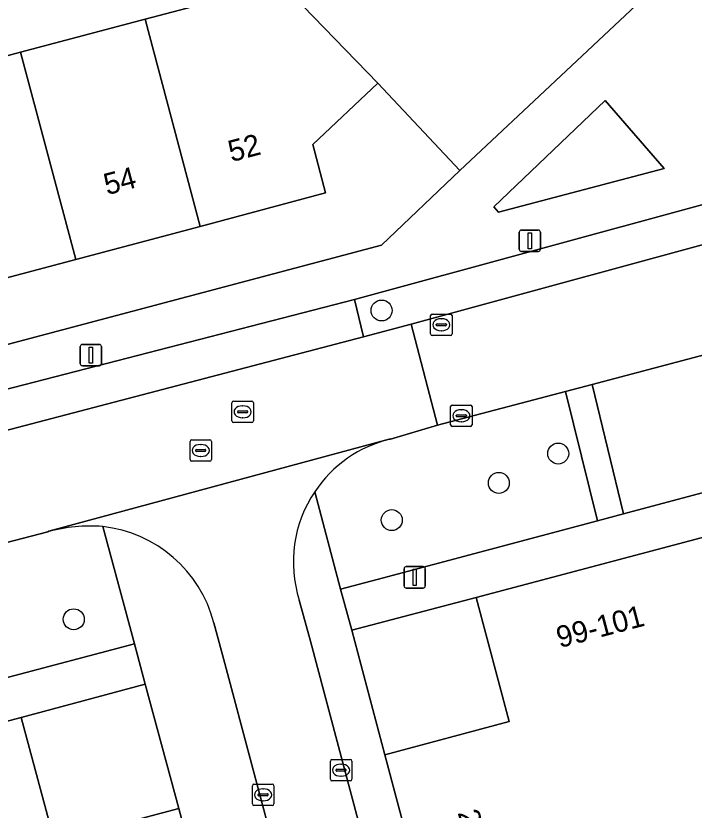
# Model space of a CAD drawing. Extents: x 162542 to 163147, y 380779 to 381521.
# Drawn here: x 162904.74 to 162936.38, y 381152.86 to 381189.91 of the extents above; entities that cross this region are included whole.
import ezdxf

# ---------------------------------------------------------------- set-up
doc = ezdxf.new("R2010")
doc.units = 0
for name, color, linetype in [('IMGEO_Boom', 7, 'Continuous'), ('IMGEO_Erf', 7, 'Continuous'), ('IMGEO_Groenvoorziening', 7, 'Continuous'), ('IMGEO_Kolk', 7, 'Continuous'), ('IMGEO_Lichtmast', 7, 'Continuous'), ('IMGEO_Muur', 7, 'Continuous'), ('IMGEO_Pand', 7, 'Continuous'), ('IMGEO_Pand_nummerreeks', 7, 'Continuous'), ('IMGEO_Parkeervlak_open', 7, 'Continuous'), ('IMGEO_Rijbaan_lokaal_open', 7, 'Continuous'), ('IMGEO_Rioolput', 7, 'Continuous'), ('IMGEO_Voetpad_open', 7, 'Continuous')]:
    doc.layers.add(name, color=color, linetype=linetype)

msp = doc.modelspace()

# ---------------------------------------------------------------- linework, layer by layer
at = {"layer": 'IMGEO_Boom'}
for centre in [(162921.8, 381176.17), (162930.038, 381169.497), (162927.268, 381168.127), (162922.276, 381166.393), (162907.441, 381161.767)]:
    msp.add_circle(centre, 0.489, dxfattribs=at)
at = {"layer": 'IMGEO_Erf'}
msp.add_lwpolyline([(162864.29, 381177.412), (162870.101, 381178.955), (162875.911, 381180.498), (162881.722, 381182.041), (162887.533, 381183.585), (162893.343, 381185.128), (162899.153, 381186.672), (162904.964, 381188.216), (162910.774, 381189.76), (162917.122, 381191.446)], dxfattribs=at)
for points in [[(162925.455, 381182.694), (162921.624, 381186.774), (162918.59, 381183.913), (162919.187, 381181.662), (162913.342, 381180.093), (162907.532, 381178.55), (162901.721, 381177.006), (162895.911, 381175.462), (162890.101, 381173.918), (162884.29, 381172.375), (162878.48, 381170.831), (162872.669, 381169.287), (162866.859, 381167.744), (162861.048, 381166.2), (162855.117, 381164.624), (162849.174, 381163.045), (162849.909, 381160.144), (162921.793, 381179.222)], [(162921.959, 381155.449), (162927.747, 381156.998), (162926.213, 381162.787), (162920.409, 381161.252)], [(162904.989, 381157.182), (162906.54, 381151.404), (162912.337, 381152.94), (162910.777, 381158.734)]]:
    msp.add_lwpolyline(points, close=True, dxfattribs=at)
at = {"layer": 'IMGEO_Groenvoorziening'}
for points in [[(162934.984, 381182.801), (162932.236, 381185.965), (162927.031, 381181), (162927.248, 381180.762)], [(162941.6, 381175.367), (162931.623, 381172.725), (162933.078, 381166.682), (162943.223, 381169.386)]]:
    msp.add_lwpolyline(points, close=True, dxfattribs=at)
for points in [[(162918.68, 381167.708), (162919.888, 381163.169), (162921.592, 381163.621), (162931.869, 381166.36), (162930.38, 381172.396)], [(162930.38, 381172.396), (162924.413, 381170.816), (162922.209, 381170.17)], [(162906.236, 381165.843), (162903.106, 381165.042), (162896.342, 381163.214), (162898.043, 381157.387), (162910.268, 381160.623), (162908.793, 381166.091)]]:
    msp.add_lwpolyline(points, dxfattribs=at)
for centre, radius, start, end in [((162923.519, 381164.532), 5.788, 103.0795, 146.7235), ((162908.186, 381159.041), 7.076, 85.0809, 105.9986)]:
    msp.add_arc(centre, radius, start, end, dxfattribs=at)
at = {"layer": 'IMGEO_Kolk'}
for p, q in [((162924.161, 381176.005), (162925.013, 381176.005)), ((162924.086, 381175.079), (162924.086, 381175.931)), ((162924.574, 381175.785), (162924.599, 381175.785)), ((162925.087, 381175.931), (162925.087, 381175.079)), ((162924.345, 381175.499), (162924.345, 381175.511)), ((162924.783, 381175.462), (162924.385, 381175.462)), ((162924.388, 381175.548), (162924.786, 381175.548)), ((162924.597, 381175.225), (162924.572, 381175.225)), ((162924.829, 381175.511), (162924.829, 381175.499)), ((162925.013, 381175.005), (162924.161, 381175.005)), ((162925.02, 381170.835), (162925.02, 381171.687)), ((162925.095, 381171.761), (162925.947, 381171.761)), ((162925.508, 381171.541), (162925.533, 381171.541)), ((162926.021, 381171.687), (162926.021, 381170.835)), ((162925.279, 381171.255), (162925.279, 381171.267)), ((162925.717, 381171.218), (162925.319, 381171.218)), ((162925.322, 381171.304), (162925.72, 381171.304)), ((162925.763, 381171.267), (162925.763, 381171.255)), ((162925.531, 381170.981), (162925.506, 381170.981)), ((162925.947, 381170.761), (162925.095, 381170.761)), ((162919.485, 381155.228), (162920.337, 381155.228)), ((162919.41, 381154.302), (162919.41, 381155.154)), ((162919.898, 381155.008), (162919.923, 381155.008)), ((162920.411, 381155.154), (162920.411, 381154.302)), ((162919.669, 381154.722), (162919.669, 381154.734)), ((162920.107, 381154.685), (162919.709, 381154.685)), ((162919.712, 381154.771), (162920.11, 381154.771)), ((162920.153, 381154.734), (162920.153, 381154.722)), ((162920.337, 381154.228), (162919.485, 381154.228)), ((162919.921, 381154.448), (162919.896, 381154.448)), ((162915.773, 381153.152), (162915.773, 381154.004)), ((162915.848, 381154.078), (162916.7, 381154.078)), ((162916.261, 381153.858), (162916.286, 381153.858)), ((162916.774, 381154.004), (162916.774, 381153.152)), ((162916.032, 381153.572), (162916.032, 381153.584)), ((162916.47, 381153.535), (162916.072, 381153.535)), ((162916.075, 381153.621), (162916.473, 381153.621)), ((162916.516, 381153.584), (162916.516, 381153.572)), ((162916.7, 381153.078), (162915.848, 381153.078)), ((162916.284, 381153.298), (162916.259, 381153.298))]:
    msp.add_line(p, q, dxfattribs=at)
for points in [[(162924.161, 381176.005), (162925.013, 381176.005)], [(162924.086, 381175.079), (162924.086, 381175.931)], [(162925.087, 381175.931), (162925.087, 381175.079)], [(162925.013, 381175.005), (162924.161, 381175.005)], [(162925.02, 381170.835), (162925.02, 381171.687)], [(162925.095, 381171.761), (162925.947, 381171.761)], [(162926.021, 381171.687), (162926.021, 381170.835)], [(162925.947, 381170.761), (162925.095, 381170.761)], [(162919.485, 381155.228), (162920.337, 381155.228)], [(162919.41, 381154.302), (162919.41, 381155.154)], [(162920.411, 381155.154), (162920.411, 381154.302)], [(162920.337, 381154.228), (162919.485, 381154.228)], [(162915.773, 381153.152), (162915.773, 381154.004)], [(162915.848, 381154.078), (162916.7, 381154.078)], [(162916.774, 381154.004), (162916.774, 381153.152)], [(162916.7, 381153.078), (162915.848, 381153.078)]]:
    msp.add_lwpolyline(points, dxfattribs=at)
for centre, radius, start, end in [((162924.163, 381175.929), 0.0765, 91.552, 178.448), ((162924.163, 381175.929), 0.0765, 91.552, 178.448), ((162925.011, 381175.929), 0.0765, 1.552, 88.448), ((162925.011, 381175.929), 0.0765, 1.552, 88.448), ((162924.385, 381175.508), 0.0403, 85.8775, 175.7526), ((162924.382, 381175.498), 0.0366, 178.938, 274.7102), ((162924.786, 381175.505), 0.043, 264.8664, 352.4533), ((162924.79, 381175.51), 0.0386, 1.7309, 96.639), ((162924.163, 381175.081), 0.0765, 181.552, 268.448), ((162924.163, 381175.081), 0.0765, 181.552, 268.448), ((162925.011, 381175.081), 0.0765, 271.552, 358.448), ((162925.011, 381175.081), 0.0765, 271.552, 358.448), ((162925.097, 381171.685), 0.0765, 91.552, 178.448), ((162925.097, 381171.685), 0.0765, 91.552, 178.448), ((162925.945, 381171.685), 0.0765, 1.552, 88.448), ((162925.945, 381171.685), 0.0765, 1.552, 88.448), ((162925.319, 381171.264), 0.0403, 85.8775, 175.7526), ((162925.316, 381171.254), 0.0366, 178.938, 274.7102), ((162925.72, 381171.261), 0.043, 264.8664, 352.4533), ((162925.724, 381171.266), 0.0386, 1.7309, 96.639), ((162925.097, 381170.837), 0.0765, 181.552, 268.448), ((162925.097, 381170.837), 0.0765, 181.552, 268.448), ((162925.945, 381170.837), 0.0765, 271.552, 358.448), ((162925.945, 381170.837), 0.0765, 271.552, 358.448), ((162919.487, 381155.152), 0.0765, 91.552, 178.448), ((162919.487, 381155.152), 0.0765, 91.552, 178.448), ((162920.335, 381155.152), 0.0765, 1.552, 88.448), ((162920.335, 381155.152), 0.0765, 1.552, 88.448), ((162919.709, 381154.731), 0.0403, 85.8775, 175.7526), ((162919.706, 381154.721), 0.0366, 178.938, 274.7102), ((162920.11, 381154.728), 0.043, 264.8664, 352.4533), ((162920.114, 381154.733), 0.0386, 1.7309, 96.639), ((162919.487, 381154.304), 0.0765, 181.552, 268.448), ((162919.487, 381154.304), 0.0765, 181.552, 268.448), ((162920.335, 381154.304), 0.0765, 271.552, 358.448), ((162920.335, 381154.304), 0.0765, 271.552, 358.448), ((162915.85, 381154.002), 0.0765, 91.552, 178.448), ((162915.85, 381154.002), 0.0765, 91.552, 178.448), ((162916.698, 381154.002), 0.0765, 1.552, 88.448), ((162916.698, 381154.002), 0.0765, 1.552, 88.448), ((162916.072, 381153.581), 0.0403, 85.8775, 175.7526), ((162916.069, 381153.571), 0.0366, 178.938, 274.7102), ((162916.473, 381153.578), 0.043, 264.8664, 352.4533), ((162916.477, 381153.583), 0.0386, 1.7309, 96.639), ((162915.85, 381153.154), 0.0765, 181.552, 268.448), ((162915.85, 381153.154), 0.0765, 181.552, 268.448), ((162916.698, 381153.154), 0.0765, 271.552, 358.448), ((162916.698, 381153.154), 0.0765, 271.552, 358.448)]:
    msp.add_arc(centre, radius, start, end, dxfattribs=at)
for centre, major_axis, ratio, start_param, end_param in [((162924.573, 381175.505), (-0.387, 0.002), 0.722429, 4.712389, 7.853982), ((162924.598, 381175.505), (-0.39, 0.002), 0.717154, 1.570796, 4.712389), ((162925.507, 381171.261), (-0.387, 0.002), 0.722429, 4.712389, 7.853982), ((162925.532, 381171.261), (-0.39, 0.002), 0.717154, 1.570796, 4.712389), ((162919.897, 381154.728), (-0.387, 0.002), 0.722429, 4.712389, 7.853982), ((162919.922, 381154.728), (-0.39, 0.002), 0.717154, 1.570796, 4.712389), ((162916.26, 381153.578), (-0.387, 0.002), 0.722429, 4.712389, 7.853982), ((162916.285, 381153.578), (-0.39, 0.002), 0.717154, 1.570796, 4.712389)]:
    msp.add_ellipse(centre, major_axis=major_axis, ratio=ratio, start_param=start_param, end_param=end_param, dxfattribs=at)
at = {"layer": 'IMGEO_Lichtmast'}
for p, q in [((162928.219, 381179.024), (162928.219, 381179.824)), ((162928.219, 381179.824), (162928.219, 381179.024)), ((162928.319, 381179.924), (162929.109, 381179.924)), ((162929.109, 381179.924), (162928.319, 381179.924)), ((162929.209, 381179.824), (162929.209, 381179.024)), ((162929.209, 381179.024), (162929.209, 381179.824)), ((162929.109, 381178.924), (162928.319, 381178.924)), ((162928.319, 381178.924), (162929.109, 381178.924)), ((162907.745, 381173.69), (162907.745, 381174.49)), ((162907.745, 381174.49), (162907.745, 381173.69)), ((162907.845, 381174.59), (162908.635, 381174.59)), ((162908.635, 381174.59), (162907.845, 381174.59)), ((162908.735, 381174.49), (162908.735, 381173.69)), ((162908.735, 381173.69), (162908.735, 381174.49)), ((162908.635, 381173.59), (162907.845, 381173.59)), ((162907.845, 381173.59), (162908.635, 381173.59)), ((162922.848, 381163.324), (162922.848, 381164.124)), ((162922.848, 381164.124), (162922.848, 381163.324)), ((162922.948, 381164.224), (162923.738, 381164.224)), ((162923.738, 381164.224), (162922.948, 381164.224)), ((162923.838, 381164.124), (162923.838, 381163.324)), ((162923.838, 381163.324), (162923.838, 381164.124)), ((162923.738, 381163.224), (162922.948, 381163.224)), ((162922.948, 381163.224), (162923.738, 381163.224))]:
    msp.add_line(p, q, dxfattribs=at)
for points in [[(162928.639, 381179.799), (162928.789, 381179.799), (162928.789, 381179.049), (162928.639, 381179.049), (162928.639, 381179.799)], [(162908.165, 381174.465), (162908.315, 381174.465), (162908.315, 381173.715), (162908.165, 381173.715), (162908.165, 381174.465)], [(162923.268, 381164.099), (162923.418, 381164.099), (162923.418, 381163.349), (162923.268, 381163.349), (162923.268, 381164.099)]]:
    msp.add_lwpolyline(points, dxfattribs=at)
for centre, start, end in [((162928.319, 381179.824), 90, 180), ((162928.319, 381179.824), 90, 180), ((162929.109, 381179.824), 0, 90), ((162929.109, 381179.824), 360, 90), ((162928.319, 381179.024), 180, 270), ((162928.319, 381179.024), 180, 270), ((162929.109, 381179.024), 270, 0), ((162929.109, 381179.024), 270, 0), ((162907.845, 381174.49), 90, 180), ((162907.845, 381174.49), 90, 180), ((162908.635, 381174.49), 0, 90), ((162908.635, 381174.49), 360, 90), ((162907.845, 381173.69), 180, 270), ((162907.845, 381173.69), 180, 270), ((162908.635, 381173.69), 270, 0), ((162908.635, 381173.69), 270, 0), ((162922.948, 381164.124), 90, 180), ((162922.948, 381164.124), 90, 180), ((162923.738, 381164.124), 0, 90), ((162923.738, 381164.124), 360, 90), ((162922.948, 381163.324), 180, 270), ((162922.948, 381163.324), 180, 270), ((162923.738, 381163.324), 270, 0), ((162923.738, 381163.324), 270, 0)]:
    msp.add_arc(centre, 0.1, start, end, dxfattribs=at)
at = {"layer": 'IMGEO_Muur'}
for points in [[(162926.213, 381162.787), (162920.409, 381161.252), (162921.959, 381155.449)], [(162910.777, 381158.734), (162904.989, 381157.182)], [(162912.337, 381152.94), (162910.777, 381158.734)]]:
    msp.add_lwpolyline(points, dxfattribs=at)
at = {"layer": 'IMGEO_Pand'}
for points in [[(162939.164, 381203.82), (162934.676, 381208.594), (162930.637, 381212.889), (162926.266, 381208.779), (162922.498, 381212.786), (162922.327, 381212.968), (162917.212, 381208.149), (162917.043, 381208.328), (162913.41, 381204.905), (162910.674, 381202.328), (162908.709, 381200.476), (162910.511, 381198.541), (162910.938, 381198.083), (162912.597, 381196.303), (162913.121, 381195.741), (162917.122, 381191.446), (162921.624, 381186.774), (162925.455, 381182.694), (162930.161, 381187.114), (162938.919, 381195.337), (162934.812, 381199.7)], [(162913.342, 381180.093), (162919.187, 381181.662), (162918.59, 381183.913), (162921.624, 381186.774), (162917.122, 381191.446), (162910.774, 381189.76)], [(162904.964, 381188.216), (162907.532, 381178.55), (162913.342, 381180.093), (162910.774, 381189.76)], [(162901.721, 381177.006), (162907.532, 381178.55), (162904.964, 381188.216), (162899.153, 381186.672)], [(162947.385, 381154.948), (162945.58, 381161.738), (162945.126, 381161.616), (162942.447, 381160.897), (162939.768, 381160.178), (162938.228, 381165.977), (162926.213, 381162.787), (162927.747, 381156.998), (162921.959, 381155.449), (162925.16, 381143.411), (162930.943, 381144.949), (162932.49, 381139.157), (162944.529, 381142.345), (162943.016, 381148.152), (162948.785, 381149.681), (162948.742, 381149.846)], [(162912.337, 381152.94), (162906.54, 381151.404), (162904.989, 381157.182), (162892.949, 381153.986), (162894.491, 381148.211), (162889.15, 381146.754), (162890.948, 381139.991), (162892.347, 381134.732), (162897.698, 381136.153), (162899.268, 381130.359), (162911.299, 381133.566), (162909.754, 381139.342), (162915.553, 381140.895)]]:
    msp.add_lwpolyline(points, close=True, dxfattribs=at)
at = {"layer": 'IMGEO_Parkeervlak_open'}
for points in [[(162945.307, 381183.409), (162944.204, 381183.118), (162943.854, 381183.025), (162937.074, 381181.191), (162920.542, 381176.676), (162920.963, 381174.947), (162923.178, 381175.528), (162939.834, 381180.075), (163029.671, 381203.749), (163029.17, 381205.595), (163009.881, 381200.547), (163008.469, 381200.178), (162968.263, 381189.504)], [(162920.963, 381174.947), (162920.542, 381176.676), (162903.648, 381172.331), (162904.167, 381170.544)]]:
    msp.add_lwpolyline(points, close=True, dxfattribs=at)
msp.add_lwpolyline([(162908.793, 381166.091), (162910.268, 381160.623), (162910.777, 381158.734), (162912.337, 381152.94), (162915.553, 381140.895), (162917.102, 381135.094), (162920.792, 381136.062), (162914.487, 381159.706), (162913.973, 381161.602)], dxfattribs=at)
msp.add_arc((162908.139, 381160.103), 6.023, 14.4079, 83.7675, dxfattribs=at)
at = {"layer": 'IMGEO_Rijbaan_lokaal_open'}
for points in [[(163029.671, 381203.749), (162939.834, 381180.075), (162923.178, 381175.528), (162924.413, 381170.816), (162930.38, 381172.396), (162931.623, 381172.725), (162941.6, 381175.367), (162946.927, 381176.777), (162948.093, 381177.085), (162958.186, 381179.749), (162960.101, 381180.253), (162970.109, 381182.891), (162971.268, 381183.196), (162981.715, 381185.95), (162982.865, 381186.253), (162993.306, 381189.004), (162994.468, 381189.311), (163004.787, 381192.03)], [(162922.209, 381170.17), (162922.157, 381170.174), (162906.287, 381165.874), (162906.236, 381165.843)], [(162918.477, 381160.741), (162917.962, 381162.664)], [(162913.973, 381161.602), (162914.487, 381159.706), (162920.792, 381136.062), (162924.771, 381137.113), (162918.477, 381160.741)]]:
    msp.add_lwpolyline(points, dxfattribs=at)
msp.add_lwpolyline([(162922.157, 381170.174), (162922.209, 381170.17), (162924.413, 381170.816), (162923.178, 381175.528), (162920.963, 381174.947), (162904.167, 381170.544), (162901.876, 381169.92), (162903.106, 381165.042), (162906.236, 381165.843), (162906.287, 381165.874)], close=True, dxfattribs=at)
for centre, radius, start, end in [((162923.519, 381164.532), 5.788, 103.0795, 146.7235), ((162923.504, 381164.448), 5.822, 145.9507, 197.8464), ((162908.186, 381159.041), 7.076, 85.0809, 105.9986), ((162908.139, 381160.103), 6.023, 14.4079, 83.7675)]:
    msp.add_arc(centre, radius, start, end, dxfattribs=at)
at = {"layer": 'IMGEO_Rioolput'}
for p, q in [((162914.892, 381171.944), (162915.744, 381171.944)), ((162914.817, 381171.018), (162914.817, 381171.87)), ((162915.305, 381171.724), (162915.33, 381171.724)), ((162915.818, 381171.87), (162915.818, 381171.018)), ((162915.076, 381171.438), (162915.076, 381171.45)), ((162915.514, 381171.401), (162915.116, 381171.401)), ((162915.119, 381171.487), (162915.517, 381171.487)), ((162915.328, 381171.164), (162915.303, 381171.164)), ((162915.56, 381171.45), (162915.56, 381171.438)), ((162915.744, 381170.944), (162914.892, 381170.944)), ((162912.864, 381169.214), (162912.864, 381170.066)), ((162912.939, 381170.14), (162913.791, 381170.14)), ((162913.865, 381170.066), (162913.865, 381169.214)), ((162913.166, 381169.683), (162913.564, 381169.683)), ((162913.352, 381169.92), (162913.377, 381169.92)), ((162913.123, 381169.634), (162913.123, 381169.646)), ((162913.561, 381169.597), (162913.163, 381169.597)), ((162913.375, 381169.36), (162913.35, 381169.36)), ((162913.607, 381169.646), (162913.607, 381169.634)), ((162913.791, 381169.14), (162912.939, 381169.14))]:
    msp.add_line(p, q, dxfattribs=at)
for points in [[(162914.892, 381171.944), (162915.744, 381171.944)], [(162914.817, 381171.018), (162914.817, 381171.87)], [(162915.818, 381171.87), (162915.818, 381171.018)], [(162915.744, 381170.944), (162914.892, 381170.944)], [(162912.864, 381169.214), (162912.864, 381170.066)], [(162912.939, 381170.14), (162913.791, 381170.14)], [(162913.865, 381170.066), (162913.865, 381169.214)], [(162913.791, 381169.14), (162912.939, 381169.14)]]:
    msp.add_lwpolyline(points, dxfattribs=at)
for centre, radius, start, end in [((162914.894, 381171.868), 0.0765, 91.552, 178.448), ((162914.894, 381171.868), 0.0765, 91.552, 178.448), ((162915.742, 381171.868), 0.0765, 1.552, 88.448), ((162915.742, 381171.868), 0.0765, 1.552, 88.448), ((162915.116, 381171.447), 0.0403, 85.8775, 175.7526), ((162915.113, 381171.437), 0.0366, 178.938, 274.7102), ((162915.517, 381171.444), 0.043, 264.8664, 352.4533), ((162915.521, 381171.449), 0.0386, 1.7309, 96.639), ((162914.894, 381171.02), 0.0765, 181.552, 268.448), ((162914.894, 381171.02), 0.0765, 181.552, 268.448), ((162915.742, 381171.02), 0.0765, 271.552, 358.448), ((162915.742, 381171.02), 0.0765, 271.552, 358.448), ((162912.941, 381170.064), 0.0765, 91.552, 178.448), ((162912.941, 381170.064), 0.0765, 91.552, 178.448), ((162913.789, 381170.064), 0.0765, 1.552, 88.448), ((162913.789, 381170.064), 0.0765, 1.552, 88.448), ((162913.163, 381169.643), 0.0403, 85.8775, 175.7526), ((162913.568, 381169.645), 0.0386, 1.7309, 96.639), ((162913.16, 381169.633), 0.0366, 178.938, 274.7102), ((162913.564, 381169.64), 0.043, 264.8664, 352.4533), ((162912.941, 381169.216), 0.0765, 181.552, 268.448), ((162912.941, 381169.216), 0.0765, 181.552, 268.448), ((162913.789, 381169.216), 0.0765, 271.552, 358.448), ((162913.789, 381169.216), 0.0765, 271.552, 358.448)]:
    msp.add_arc(centre, radius, start, end, dxfattribs=at)
for centre, major_axis, ratio, start_param, end_param in [((162915.304, 381171.444), (-0.387, 0.002), 0.722429, 4.712389, 7.853982), ((162915.329, 381171.444), (-0.39, 0.002), 0.717154, 1.570796, 4.712389), ((162913.351, 381169.64), (-0.387, 0.002), 0.722429, 4.712389, 7.853982), ((162913.376, 381169.64), (-0.39, 0.002), 0.717154, 1.570796, 4.712389)]:
    msp.add_ellipse(centre, major_axis=major_axis, ratio=ratio, start_param=start_param, end_param=end_param, dxfattribs=at)
at = {"layer": 'IMGEO_Voetpad_open'}
for points in [[(162865.48, 381282.064), (162871.275, 381275.979), (162871.311, 381275.941), (162873.07, 381274.077), (162878.582, 381268.238), (162880.297, 381266.406), (162887.54, 381258.657), (162894.031, 381251.782), (162897.699, 381247.866), (162926.773, 381216.999), (162930.637, 381212.889), (162934.676, 381208.594), (162939.164, 381203.82), (162943.3, 381199.444), (162938.919, 381195.337), (162930.161, 381187.114), (162925.455, 381182.694), (162921.793, 381179.222), (162849.909, 381160.144)], [(162850.91, 381158.201), (162882.303, 381166.521), (162903.648, 381172.331), (162920.542, 381176.676), (162937.074, 381181.191), (162936.958, 381181.61), (162944.091, 381183.522), (162944.204, 381183.118), (162945.307, 381183.409), (162968.263, 381189.504), (162966.757, 381191.138), (162965.477, 381192.532), (162963.89, 381194.094), (162959.774, 381198.46), (162951.248, 381207.533), (162947.383, 381211.626), (162906.029, 381255.574)], [(163006.379, 381186.176), (162996.039, 381183.424), (162994.892, 381183.118), (162984.447, 381180.339), (162983.289, 381180.032), (162972.863, 381177.268), (162971.713, 381176.963), (162961.683, 381174.305), (162959.78, 381173.79), (162949.683, 381171.106), (162948.531, 381170.8), (162943.223, 381169.386), (162933.078, 381166.682), (162931.869, 381166.36), (162921.592, 381163.621), (162919.888, 381163.169), (162920.409, 381161.252), (162926.213, 381162.787), (162938.228, 381165.977), (162943.75, 381167.455), (163005.842, 381183.958)], [(162917.962, 381162.664), (162918.477, 381160.741), (162924.771, 381137.113), (162926.69, 381137.622), (162925.16, 381143.411), (162921.959, 381155.449), (162920.409, 381161.252), (162919.888, 381163.169), (162918.68, 381167.708)], [(162887.505, 381152.528), (162892.949, 381153.986), (162904.989, 381157.182), (162910.777, 381158.734), (162910.268, 381160.623), (162898.043, 381157.387), (162896.875, 381157.078), (162887.685, 381154.645), (162875.889, 381151.523)]]:
    msp.add_lwpolyline(points, dxfattribs=at)
for points in [[(162932.236, 381185.965), (162934.984, 381182.801), (162927.248, 381180.762), (162927.031, 381181)], [(162931.623, 381172.725), (162930.38, 381172.396), (162931.869, 381166.36), (162933.078, 381166.682)]]:
    msp.add_lwpolyline(points, close=True, dxfattribs=at)
msp.add_arc((162923.504, 381164.448), 5.822, 145.9507, 197.8464, dxfattribs=at)

# ---------------------------------------------------------------- texts
at = {"layer": 'IMGEO_Pand_nummerreeks'}
for s, rotation, p in [('52', 14.8786, (162914.798, 381183.088)), ('54', 14.8786, (162908.994, 381181.546)), ('99-101', 14.7422, (162930.106, 381160.42)), ('29-35', 285.2004, (162925.343, 381152.75))]:
    msp.add_text(s, height=1, rotation=rotation, dxfattribs=at).set_placement(p)

doc.saveas('drawing.dxf')
